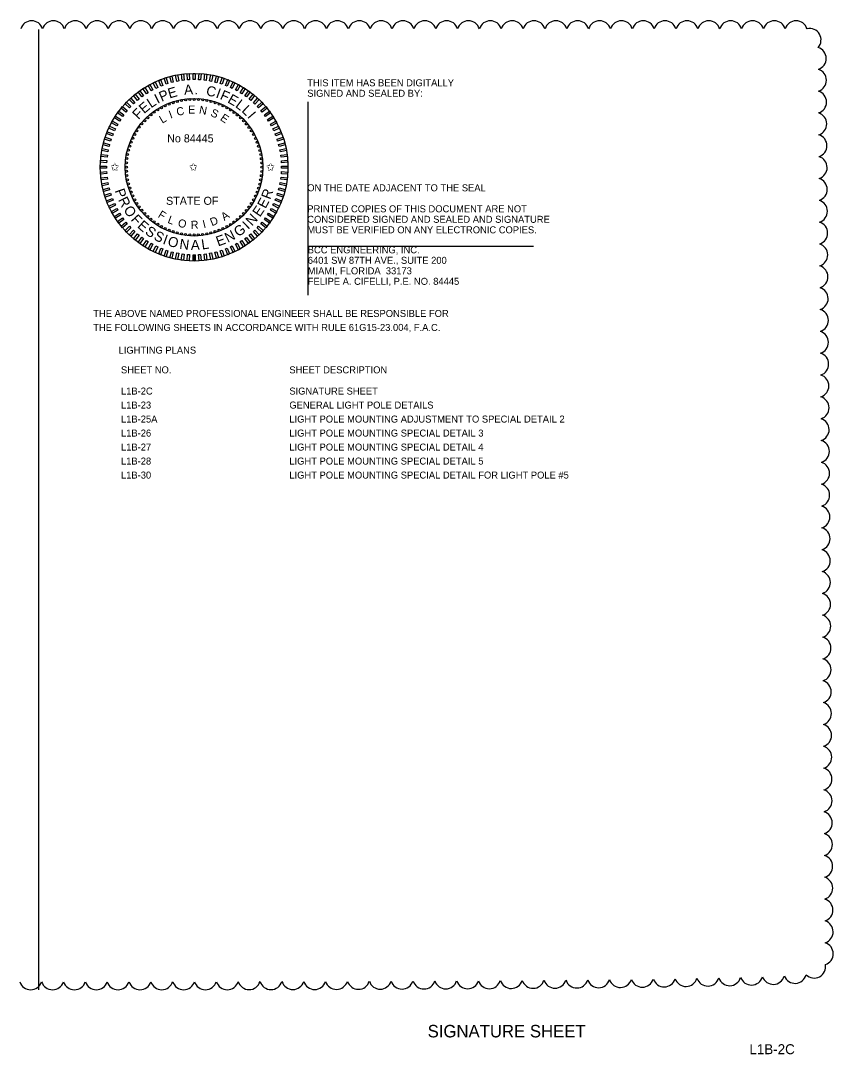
# Model space of a CAD drawing. Extents: x -811.2 to -795, y -2307.6 to -2235.1.
# Drawn here: x -803.27 to -795.14, y -2282.69 to -2272.36 of the extents above; entities that cross this region are included whole.
import ezdxf

# ---------------------------------------------------------------- set-up
doc = ezdxf.new("R2010")
doc.units = 0
for name, color, linetype in [('AdhocPoint_dp', 7, 'Continuous'), ('Cloud_dp', 7, 'Continuous'), ('Logo_dp', 7, 'Continuous'), ('NonPlottingEle_dp', 7, 'Continuous'), ('TeleMisc', 7, 'Continuous'), ('TextDetails', 7, 'Continuous'), ('TextMisc', 7, 'Continuous'), ('TextNotes', 7, 'Continuous')]:
    doc.layers.add(name, color=color, linetype=linetype)

msp = doc.modelspace()

# ---------------------------------------------------------------- linework, layer by layer
at = {"layer": 'AdhocPoint_dp'}
for p, q in [((-800.397, -2273.168), (-800.397, -2275.103)), ((-800.397, -2274.613), (-798.141, -2274.613))]:
    msp.add_line(p, q, dxfattribs=at)
at = {"layer": 'Cloud_dp'}
for centre, start, end in [((-803.157, -2272.472), 17.5, 162.5), ((-802.939, -2272.472), 17.5, 162.5), ((-802.721, -2272.472), 17.5, 162.5), ((-802.502, -2272.472), 17.5, 162.5), ((-802.284, -2272.472), 17.5, 162.5), ((-802.066, -2272.472), 17.5, 162.5), ((-801.847, -2272.472), 17.5, 162.5), ((-801.629, -2272.472), 17.5, 162.5), ((-801.411, -2272.472), 17.5, 162.5), ((-801.192, -2272.472), 17.5, 162.5), ((-800.974, -2272.472), 17.5, 162.5), ((-800.756, -2272.472), 17.5, 162.5), ((-800.537, -2272.472), 17.5, 162.5), ((-800.319, -2272.472), 17.5, 162.5), ((-800.101, -2272.472), 17.5, 162.5), ((-799.882, -2272.472), 17.5, 162.5), ((-799.664, -2272.472), 17.5, 162.5), ((-799.446, -2272.472), 17.5, 162.5), ((-799.227, -2272.472), 17.5, 162.5), ((-799.009, -2272.472), 17.5, 162.5), ((-798.791, -2272.472), 17.5, 162.5), ((-798.572, -2272.472), 17.5, 162.5), ((-798.354, -2272.472), 17.5, 162.5), ((-798.136, -2272.472), 17.5, 162.5), ((-797.917, -2272.472), 17.5, 162.5), ((-797.699, -2272.472), 17.5, 162.5), ((-797.481, -2272.472), 17.5, 162.5), ((-797.262, -2272.472), 17.5, 162.5), ((-797.044, -2272.472), 17.5, 162.5), ((-796.826, -2272.472), 17.5, 162.5), ((-796.607, -2272.472), 17.5, 162.5), ((-796.389, -2272.472), 17.5, 162.5), ((-796.171, -2272.472), 17.5, 162.5), ((-795.952, -2272.472), 17.5, 162.5), ((-795.734, -2272.472), 17.5, 162.5), ((-795.516, -2272.472), 17.5, 162.5), ((-795.381, -2272.549), 318.1116, 103.1116), ((-795.329, -2272.734), 287.9529, 72.9529), ((-795.327, -2272.953), 287.9529, 72.9529), ((-795.326, -2273.171), 287.9529, 72.9529), ((-795.324, -2273.389), 287.9529, 72.9529), ((-795.322, -2273.608), 287.9529, 72.9529), ((-795.32, -2273.826), 287.9529, 72.9529), ((-795.319, -2274.044), 287.9529, 72.9529), ((-795.317, -2274.263), 287.9529, 72.9529), ((-795.315, -2274.481), 287.9529, 72.9529), ((-795.314, -2274.699), 287.9529, 72.9529), ((-795.312, -2274.918), 287.9529, 72.9529), ((-795.31, -2275.136), 287.9529, 72.9529), ((-795.308, -2275.354), 287.9529, 72.9529), ((-795.307, -2275.573), 287.9529, 72.9529), ((-795.305, -2275.791), 287.9529, 72.9529), ((-795.303, -2276.009), 287.9529, 72.9529), ((-795.301, -2276.228), 287.9529, 72.9529), ((-795.3, -2276.446), 287.9529, 72.9529), ((-795.298, -2276.664), 287.9529, 72.9529), ((-795.296, -2276.882), 287.9529, 72.9529), ((-795.295, -2277.101), 287.9529, 72.9529), ((-795.293, -2277.319), 287.9527, 72.9527), ((-795.291, -2277.537), 287.9524, 72.9524), ((-795.289, -2277.756), 287.9521, 72.9521), ((-795.288, -2277.974), 287.9519, 72.9519), ((-795.286, -2278.192), 287.9515, 72.9515), ((-795.284, -2278.411), 287.9512, 72.9512), ((-795.282, -2278.629), 287.9508, 72.9508), ((-795.281, -2278.847), 287.9504, 72.9504), ((-795.279, -2279.066), 287.9499, 72.9499), ((-795.277, -2279.284), 287.9494, 72.9494), ((-795.276, -2279.502), 287.9488, 72.9488), ((-795.274, -2279.721), 287.9481, 72.9481), ((-795.272, -2279.939), 287.9473, 72.9473), ((-795.271, -2280.157), 287.9464, 72.9464), ((-795.269, -2280.376), 287.9452, 72.9452), ((-795.267, -2280.594), 287.9438, 72.9438), ((-795.265, -2280.812), 287.9419, 72.9419), ((-795.264, -2281.03), 287.9394, 72.9394), ((-795.262, -2281.249), 287.9355, 72.9355), ((-795.26, -2281.467), 287.9288, 72.9288), ((-795.259, -2281.685), 287.9106, 72.9106), ((-795.336, -2281.815), 225.4798, 10.4798), ((-803.166, -2281.932), 197.496, 342.496), ((-802.948, -2281.932), 197.5011, 342.5011), ((-802.729, -2281.932), 197.5111, 342.5111), ((-802.511, -2281.932), 197.522, 342.522), ((-802.293, -2281.932), 197.5335, 342.5335), ((-802.074, -2281.932), 197.5456, 342.5456), ((-801.856, -2281.931), 197.5582, 342.5582), ((-801.638, -2281.931), 197.5715, 342.5715), ((-801.42, -2281.931), 197.5855, 342.5855), ((-801.201, -2281.931), 197.6002, 342.6002), ((-800.983, -2281.93), 197.6157, 342.6157), ((-800.765, -2281.93), 197.6322, 342.6322), ((-800.546, -2281.929), 197.6497, 342.6497), ((-800.328, -2281.929), 197.6683, 342.6683), ((-800.11, -2281.928), 197.6881, 342.6881), ((-799.891, -2281.927), 197.7093, 342.7093), ((-799.673, -2281.926), 197.732, 342.732), ((-799.455, -2281.925), 197.7565, 342.7565), ((-799.236, -2281.924), 197.7829, 342.7829), ((-799.018, -2281.923), 197.8116, 342.8116), ((-798.8, -2281.922), 197.8429, 342.8429), ((-798.582, -2281.921), 197.8771, 342.8771), ((-798.363, -2281.919), 197.9149, 342.9149), ((-798.145, -2281.917), 197.9569, 342.9569), ((-797.927, -2281.916), 198.0039, 343.0039), ((-797.708, -2281.914), 198.0569, 343.0569), ((-797.49, -2281.911), 198.1174, 343.1174), ((-797.272, -2281.909), 198.1874, 343.1874), ((-797.054, -2281.906), 198.2696, 343.2696), ((-796.835, -2281.903), 198.368, 343.368), ((-796.617, -2281.899), 198.4888, 343.4888), ((-796.399, -2281.895), 198.642, 343.642), ((-796.181, -2281.891), 198.8454, 343.8454), ((-795.963, -2281.885), 199.1345, 344.1345), ((-795.745, -2281.878), 199.5943, 344.5943), ((-795.527, -2281.868), 200.5167, 345.5167)]:
    msp.add_arc(centre, 0.114, start, end, dxfattribs=at)
at = {"layer": 'TextDetails'}
for radius in [0.938, 0.688]:
    msp.add_circle((-801.533, -2273.822), radius, dxfattribs=at)
at = {"layer": 'TextMisc'}
for p, q in [((-801.543, -2274.759), (-801.543, -2274.697)), ((-801.533, -2274.759), (-801.533, -2274.697)), ((-801.523, -2274.759), (-801.523, -2274.696))]:
    msp.add_line(p, q, dxfattribs=at)
for points in [[(-801.578, -2272.948), (-801.598, -2272.949), (-801.602, -2272.887), (-801.582, -2272.885)], [(-801.523, -2272.946), (-801.543, -2272.946), (-801.543, -2272.884), (-801.523, -2272.884)], [(-801.468, -2272.949), (-801.488, -2272.948), (-801.484, -2272.885), (-801.464, -2272.887)], [(-801.896, -2273.025), (-801.915, -2273.034), (-801.941, -2272.978), (-801.923, -2272.969)], [(-801.846, -2273.004), (-801.864, -2273.012), (-801.887, -2272.954), (-801.869, -2272.946)], [(-801.794, -2272.986), (-801.813, -2272.992), (-801.832, -2272.933), (-801.813, -2272.927)], [(-801.741, -2272.971), (-801.76, -2272.976), (-801.776, -2272.916), (-801.756, -2272.911)], [(-801.687, -2272.96), (-801.707, -2272.964), (-801.718, -2272.903), (-801.699, -2272.899)], [(-801.632, -2272.952), (-801.653, -2272.955), (-801.66, -2272.893), (-801.64, -2272.89)], [(-801.413, -2272.955), (-801.433, -2272.952), (-801.425, -2272.89), (-801.405, -2272.893)], [(-801.359, -2272.964), (-801.379, -2272.96), (-801.367, -2272.899), (-801.347, -2272.903)], [(-801.305, -2272.977), (-801.325, -2272.971), (-801.309, -2272.911), (-801.29, -2272.916)], [(-801.253, -2272.992), (-801.272, -2272.986), (-801.253, -2272.927), (-801.234, -2272.933)], [(-801.201, -2273.012), (-801.22, -2273.004), (-801.197, -2272.946), (-801.178, -2272.954)], [(-801.151, -2273.034), (-801.169, -2273.025), (-801.143, -2272.969), (-801.125, -2272.978)], [(-802.083, -2273.141), (-802.098, -2273.154), (-802.138, -2273.106), (-802.123, -2273.093)], [(-802.039, -2273.108), (-802.055, -2273.119), (-802.092, -2273.069), (-802.076, -2273.057)], [(-801.993, -2273.077), (-802.01, -2273.088), (-802.044, -2273.035), (-802.027, -2273.025)], [(-801.946, -2273.05), (-801.963, -2273.06), (-801.993, -2273.005), (-801.976, -2272.995)], [(-801.102, -2273.06), (-801.12, -2273.05), (-801.09, -2272.995), (-801.072, -2273.005)], [(-801.055, -2273.088), (-801.073, -2273.077), (-801.039, -2273.025), (-801.022, -2273.035)], [(-801.01, -2273.12), (-801.027, -2273.108), (-800.99, -2273.057), (-800.974, -2273.069)], [(-800.967, -2273.154), (-800.983, -2273.141), (-800.943, -2273.093), (-800.928, -2273.106)], [(-802.164, -2273.215), (-802.178, -2273.23), (-802.223, -2273.187), (-802.209, -2273.172)], [(-802.124, -2273.177), (-802.139, -2273.19), (-802.182, -2273.145), (-802.167, -2273.131)], [(-800.926, -2273.191), (-800.941, -2273.177), (-800.898, -2273.131), (-800.884, -2273.145)], [(-800.888, -2273.23), (-800.902, -2273.215), (-800.856, -2273.172), (-800.843, -2273.187)], [(-802.235, -2273.299), (-802.247, -2273.315), (-802.297, -2273.279), (-802.285, -2273.262)], [(-802.201, -2273.256), (-802.214, -2273.271), (-802.262, -2273.232), (-802.249, -2273.216)], [(-800.852, -2273.272), (-800.865, -2273.256), (-800.817, -2273.216), (-800.804, -2273.232)], [(-800.819, -2273.315), (-800.831, -2273.299), (-800.78, -2273.262), (-800.769, -2273.279)], [(-802.295, -2273.391), (-802.305, -2273.409), (-802.359, -2273.379), (-802.35, -2273.361)], [(-802.266, -2273.344), (-802.277, -2273.361), (-802.33, -2273.328), (-802.319, -2273.311)], [(-800.789, -2273.361), (-800.799, -2273.344), (-800.747, -2273.311), (-800.736, -2273.328)], [(-800.761, -2273.409), (-800.771, -2273.391), (-800.716, -2273.361), (-800.707, -2273.379)], [(-802.343, -2273.49), (-802.35, -2273.509), (-802.408, -2273.486), (-802.401, -2273.467)], [(-802.32, -2273.44), (-802.329, -2273.458), (-802.385, -2273.431), (-802.377, -2273.413)], [(-800.737, -2273.458), (-800.745, -2273.44), (-800.689, -2273.413), (-800.68, -2273.432)], [(-800.716, -2273.509), (-800.723, -2273.49), (-800.665, -2273.467), (-800.658, -2273.486)], [(-802.378, -2273.594), (-802.383, -2273.614), (-802.443, -2273.598), (-802.438, -2273.579)], [(-802.362, -2273.541), (-802.368, -2273.561), (-802.428, -2273.541), (-802.421, -2273.522)], [(-800.698, -2273.561), (-800.704, -2273.542), (-800.644, -2273.522), (-800.638, -2273.542)], [(-800.683, -2273.614), (-800.688, -2273.594), (-800.627, -2273.579), (-800.622, -2273.598)], [(-802.4, -2273.702), (-802.402, -2273.722), (-802.464, -2273.714), (-802.462, -2273.694)], [(-802.391, -2273.648), (-802.394, -2273.667), (-802.456, -2273.656), (-802.452, -2273.636)], [(-800.671, -2273.668), (-800.675, -2273.648), (-800.614, -2273.636), (-800.61, -2273.656)], [(-800.664, -2273.722), (-800.666, -2273.702), (-800.604, -2273.694), (-800.602, -2273.714)], [(-802.408, -2273.811), (-802.408, -2273.832), (-802.47, -2273.832), (-802.47, -2273.811)], [(-802.406, -2273.756), (-802.407, -2273.777), (-802.469, -2273.773), (-802.468, -2273.752)], [(-800.659, -2273.777), (-800.66, -2273.757), (-800.598, -2273.753), (-800.597, -2273.773)], [(-800.658, -2273.832), (-800.658, -2273.812), (-800.595, -2273.812), (-800.595, -2273.832)], [(-802.407, -2273.866), (-802.406, -2273.886), (-802.468, -2273.89), (-802.469, -2273.87)], [(-802.402, -2273.921), (-802.4, -2273.941), (-802.462, -2273.949), (-802.464, -2273.929)], [(-800.66, -2273.887), (-800.659, -2273.866), (-800.597, -2273.87), (-800.598, -2273.891)], [(-802.394, -2273.975), (-802.391, -2273.995), (-802.452, -2274.007), (-802.456, -2273.987)], [(-800.675, -2273.995), (-800.672, -2273.976), (-800.61, -2273.987), (-800.614, -2274.007)], [(-800.666, -2273.941), (-800.664, -2273.921), (-800.602, -2273.929), (-800.604, -2273.949)], [(-802.383, -2274.029), (-802.378, -2274.049), (-802.438, -2274.064), (-802.443, -2274.045)], [(-802.368, -2274.082), (-802.362, -2274.101), (-802.421, -2274.121), (-802.428, -2274.102)], [(-800.704, -2274.102), (-800.698, -2274.082), (-800.638, -2274.102), (-800.644, -2274.121)], [(-800.688, -2274.049), (-800.683, -2274.029), (-800.622, -2274.045), (-800.627, -2274.065)], [(-802.35, -2274.134), (-802.343, -2274.153), (-802.401, -2274.176), (-802.408, -2274.157)], [(-802.329, -2274.185), (-802.32, -2274.203), (-802.377, -2274.23), (-802.386, -2274.211)], [(-800.746, -2274.203), (-800.737, -2274.185), (-800.68, -2274.212), (-800.689, -2274.23)], [(-800.723, -2274.153), (-800.716, -2274.134), (-800.658, -2274.157), (-800.665, -2274.176)], [(-802.305, -2274.234), (-802.295, -2274.252), (-802.35, -2274.282), (-802.359, -2274.264)], [(-802.277, -2274.282), (-802.266, -2274.299), (-802.319, -2274.332), (-802.33, -2274.315)], [(-802.247, -2274.328), (-802.235, -2274.344), (-802.285, -2274.381), (-802.297, -2274.364)], [(-800.831, -2274.344), (-800.819, -2274.328), (-800.769, -2274.364), (-800.78, -2274.381)], [(-800.8, -2274.299), (-800.789, -2274.282), (-800.736, -2274.315), (-800.747, -2274.332)], [(-800.771, -2274.252), (-800.761, -2274.234), (-800.707, -2274.264), (-800.716, -2274.282)], [(-802.214, -2274.371), (-802.201, -2274.387), (-802.249, -2274.427), (-802.262, -2274.411)], [(-802.178, -2274.413), (-802.164, -2274.428), (-802.209, -2274.471), (-802.223, -2274.456)], [(-800.902, -2274.428), (-800.888, -2274.413), (-800.843, -2274.456), (-800.857, -2274.471)], [(-800.865, -2274.387), (-800.852, -2274.372), (-800.804, -2274.411), (-800.817, -2274.427)], [(-802.139, -2274.452), (-802.125, -2274.466), (-802.167, -2274.512), (-802.182, -2274.498)], [(-802.099, -2274.489), (-802.083, -2274.502), (-802.123, -2274.55), (-802.138, -2274.537)], [(-802.055, -2274.523), (-802.039, -2274.535), (-802.076, -2274.586), (-802.092, -2274.574)], [(-801.027, -2274.535), (-801.011, -2274.524), (-800.974, -2274.574), (-800.99, -2274.586)], [(-800.983, -2274.502), (-800.967, -2274.489), (-800.928, -2274.537), (-800.943, -2274.55)], [(-800.941, -2274.466), (-800.927, -2274.453), (-800.884, -2274.498), (-800.899, -2274.512)], [(-802.01, -2274.555), (-801.993, -2274.566), (-802.027, -2274.618), (-802.044, -2274.608)], [(-801.963, -2274.583), (-801.946, -2274.593), (-801.976, -2274.648), (-801.993, -2274.638)], [(-801.915, -2274.609), (-801.896, -2274.618), (-801.923, -2274.674), (-801.941, -2274.665)], [(-801.865, -2274.631), (-801.846, -2274.639), (-801.869, -2274.697), (-801.887, -2274.689)], [(-801.22, -2274.639), (-801.202, -2274.631), (-801.179, -2274.689), (-801.197, -2274.697)], [(-801.17, -2274.618), (-801.151, -2274.609), (-801.125, -2274.665), (-801.143, -2274.674)], [(-801.12, -2274.593), (-801.103, -2274.583), (-801.073, -2274.638), (-801.09, -2274.648)], [(-801.073, -2274.566), (-801.056, -2274.555), (-801.022, -2274.608), (-801.039, -2274.618)], [(-801.813, -2274.651), (-801.794, -2274.657), (-801.813, -2274.716), (-801.832, -2274.71)], [(-801.76, -2274.667), (-801.741, -2274.672), (-801.756, -2274.732), (-801.776, -2274.727)], [(-801.707, -2274.679), (-801.687, -2274.683), (-801.699, -2274.744), (-801.719, -2274.74)], [(-801.653, -2274.688), (-801.633, -2274.691), (-801.64, -2274.753), (-801.661, -2274.75)], [(-801.598, -2274.694), (-801.578, -2274.695), (-801.582, -2274.758), (-801.602, -2274.756)], [(-801.543, -2274.697), (-801.523, -2274.697), (-801.523, -2274.759), (-801.543, -2274.759)], [(-801.488, -2274.695), (-801.468, -2274.694), (-801.464, -2274.756), (-801.484, -2274.758)], [(-801.433, -2274.691), (-801.413, -2274.688), (-801.406, -2274.75), (-801.426, -2274.753)], [(-801.379, -2274.683), (-801.359, -2274.679), (-801.347, -2274.74), (-801.367, -2274.744)], [(-801.325, -2274.672), (-801.306, -2274.667), (-801.29, -2274.727), (-801.31, -2274.732)], [(-801.272, -2274.657), (-801.253, -2274.651), (-801.234, -2274.71), (-801.253, -2274.716)]]:
    msp.add_lwpolyline(points, close=True, dxfattribs=at)
for centre in [(-801.782, -2273.191), (-801.742, -2273.177), (-801.701, -2273.165), (-801.659, -2273.156), (-801.617, -2273.149), (-801.575, -2273.145), (-801.532, -2273.144), (-801.49, -2273.145), (-801.447, -2273.149), (-801.405, -2273.156), (-801.364, -2273.165), (-801.323, -2273.177), (-801.283, -2273.192), (-801.964, -2273.299), (-801.931, -2273.273), (-801.895, -2273.249), (-801.859, -2273.228), (-801.821, -2273.208), (-801.244, -2273.209), (-801.206, -2273.228), (-801.169, -2273.25), (-801.134, -2273.274), (-801.101, -2273.3), (-802.055, -2273.389), (-802.026, -2273.357), (-801.996, -2273.327), (-801.069, -2273.328), (-801.039, -2273.358), (-801.011, -2273.39), (-802.126, -2273.495), (-802.105, -2273.458), (-802.081, -2273.423), (-800.985, -2273.424), (-800.961, -2273.459), (-800.939, -2273.496), (-802.177, -2273.612), (-802.163, -2273.572), (-802.146, -2273.533), (-800.92, -2273.534), (-800.903, -2273.573), (-800.888, -2273.613), (-802.198, -2273.694), (-802.189, -2273.652), (-800.877, -2273.654), (-800.867, -2273.695), (-802.21, -2273.821), (-802.209, -2273.778), (-802.205, -2273.736), (-800.861, -2273.737), (-800.857, -2273.78), (-800.855, -2273.822), (-802.209, -2273.863), (-802.205, -2273.906), (-800.861, -2273.907), (-800.857, -2273.865), (-802.198, -2273.948), (-802.189, -2273.989), (-802.177, -2274.03), (-800.889, -2274.031), (-800.877, -2273.991), (-800.868, -2273.949), (-802.163, -2274.07), (-802.146, -2274.109), (-800.92, -2274.11), (-800.903, -2274.071), (-802.127, -2274.147), (-802.105, -2274.184), (-802.081, -2274.219), (-800.985, -2274.22), (-800.961, -2274.185), (-800.94, -2274.148), (-802.055, -2274.253), (-802.027, -2274.285), (-801.997, -2274.315), (-801.965, -2274.343), (-801.102, -2274.344), (-801.07, -2274.316), (-801.039, -2274.286), (-801.011, -2274.254), (-801.932, -2274.369), (-801.896, -2274.393), (-801.86, -2274.415), (-801.822, -2274.434), (-801.245, -2274.435), (-801.207, -2274.415), (-801.17, -2274.394), (-801.135, -2274.37), (-801.783, -2274.451), (-801.743, -2274.466), (-801.702, -2274.478), (-801.66, -2274.487), (-801.618, -2274.494), (-801.576, -2274.498), (-801.533, -2274.499), (-801.491, -2274.498), (-801.449, -2274.494), (-801.407, -2274.487), (-801.365, -2274.478), (-801.324, -2274.466), (-801.284, -2274.452)]:
    msp.add_circle(centre, 0.01, dxfattribs=at)
at = {"layer": 'TextNotes'}
msp.add_line((-803.086, -2282.046), (-803.086, -2272.446), dxfattribs=at)

# ---------------------------------------------------------------- texts
at = {"layer": 'Logo_dp'}
for s, height, p in [('THIS ITEM HAS BEEN DIGITALLY', 0.07, (-800.402, -2273.013)), ('SIGNED AND SEALED BY:', 0.07, (-800.402, -2273.118)), ('ON THE DATE ADJACENT TO THE SEAL', 0.07, (-800.402, -2274.063)), ('PRINTED COPIES OF THIS DOCUMENT ARE NOT ', 0.07, (-800.402, -2274.273)), ('CONSIDERED SIGNED AND SEALED AND SIGNATURE ', 0.07, (-800.402, -2274.378)), ('MUST BE VERIFIED ON ANY ELECTRONIC COPIES.', 0.07, (-800.402, -2274.483)), ('BCC ENGINEERING, INC.', 0.07, (-800.397, -2274.683)), ('6401 SW 87TH AVE., SUITE 200', 0.07, (-800.397, -2274.788)), ('MIAMI, FLORIDA  33173', 0.07, (-800.397, -2274.893)), ('FELIPE A. CIFELLI, P.E. NO. 84445', 0.07, (-800.397, -2274.998)), ('THE ABOVE NAMED PROFESSIONAL ENGINEER SHALL BE RESPONSIBLE FOR ', 0.07, (-802.541, -2275.319)), ('THE FOLLOWING SHEETS IN ACCORDANCE WITH RULE 61G15-23.004, F.A.C.', 0.07, (-802.541, -2275.459)), ('LIGHTING PLANS', 0.07, (-802.288, -2275.686)), ('       SIGNATURE SHEET         ', 0.125, (-799.524, -2282.522))]:
    msp.add_text(s, height=height, dxfattribs=at).set_placement(p)
at = {"layer": 'NonPlottingEle_dp'}
msp.add_text('L1B-2C ', height=0.1, dxfattribs=at).set_placement((-795.983, -2282.69))
at = {"layer": 'TeleMisc'}
for s, p in [('SHEET NO.', (-802.264, -2275.883)), ('SHEET DESCRIPTION', (-800.581, -2275.883)), ('L1B-2C', (-802.264, -2276.095)), ('SIGNATURE SHEET', (-800.581, -2276.095)), ('L1B-23', (-802.264, -2276.235)), ('GENERAL LIGHT POLE DETAILS', (-800.581, -2276.235)), ('L1B-25A', (-802.264, -2276.375)), ('LIGHT POLE MOUNTING ADJUSTMENT TO SPECIAL DETAIL 2', (-800.581, -2276.375)), ('L1B-26', (-802.264, -2276.515)), ('LIGHT POLE MOUNTING SPECIAL DETAIL 3', (-800.581, -2276.515)), ('L1B-27', (-802.264, -2276.655)), ('LIGHT POLE MOUNTING SPECIAL DETAIL 4', (-800.581, -2276.655)), ('L1B-28', (-802.264, -2276.795)), ('LIGHT POLE MOUNTING SPECIAL DETAIL 5', (-800.581, -2276.795)), ('L1B-30', (-802.264, -2276.935)), ('LIGHT POLE MOUNTING SPECIAL DETAIL FOR LIGHT POLE #5', (-800.581, -2276.935))]:
    msp.add_text(s, height=0.07, dxfattribs=at).set_placement(p)
at = {"layer": 'TextMisc'}
for s, height, rotation, p in [('I', 0.1, 26.8161, (-801.898, -2273.191)), ('P', 0.1, 23.2829, (-801.858, -2273.169)), ('E', 0.1, 16.5426, (-801.779, -2273.136)), ('A', 0.1, 4.421, (-801.63, -2273.099)), ('.', 0.1, 356.654, (-801.531, -2273.093)), ('C', 0.1, 347.7999, (-801.419, -2273.102)), ('I', 0.1, 340.0631, (-801.323, -2273.124)), ('F', 0.1, 336.5299, (-801.281, -2273.138)), ('E', 0.1, 330.0796, (-801.206, -2273.171)), ('E', 0.1, 40.1214, (-802.033, -2273.292)), ('L', 0.1, 33.0792, (-801.964, -2273.234)), ('L', 0.1, 323.0373, (-801.128, -2273.216)), ('F', 0.1, 46.5718, (-802.089, -2273.351)), ('I', 0.08, 20.0117, (-801.769, -2273.337)), ('C', 0.08, 12.2025, (-801.701, -2273.31)), ('E', 0.08, 0.4186, (-801.593, -2273.286)), ('N', 0.08, 349.2914, (-801.488, -2273.285)), ('S', 0.08, 337.0221, (-801.375, -2273.307)), ('E', 0.08, 325.8663, (-801.279, -2273.347)), ('L', 0.1, 316.7742, (-801.065, -2273.263)), ('I', 0.1, 310.5111, (-801.006, -2273.318)), ('L', 0.08, 30.4021, (-801.852, -2273.388)), ('P', 0.1, 289.4055, (-802.328, -2274.056)), ('R', 0.1, 296.1458, (-802.295, -2274.148)), ('E', 0.1, 62.4712, (-800.819, -2274.242)), ('R', 0.1, 69.5134, (-800.773, -2274.151)), ('O', 0.1, 303.9671, (-802.243, -2274.248)), ('E', 0.1, 55.4289, (-800.876, -2274.326)), ('F', 0.1, 312.628, (-802.171, -2274.35)), ('F', 0.08, 328.7241, (-801.901, -2274.318)), ('L', 0.08, 339.2916, (-801.804, -2274.377)), ('D', 0.08, 22.0128, (-801.355, -2274.413)), ('A', 0.08, 34.4992, (-801.231, -2274.361)), ('N', 0.1, 47.1788, (-800.955, -2274.415)), ('E', 0.1, 319.0783, (-802.107, -2274.419)), ('S', 0.1, 326.1206, (-802.03, -2274.485)), ('O', 0.08, 349.6821, (-801.699, -2274.417)), ('R', 0.08, 2.3398, (-801.565, -2274.439)), ('I', 0.08, 14.2037, (-801.437, -2274.432)), ('G', 0.1, 35.1115, (-801.092, -2274.523)), ('I', 0.1, 43.6456, (-800.993, -2274.45)), ('S', 0.1, 333.193, (-801.944, -2274.541)), ('I', 0.1, 340.2654, (-801.853, -2274.586)), ('O', 0.1, 343.7986, (-801.805, -2274.604)), ('N', 0.1, 352.4595, (-801.684, -2274.636)), ('E', 0.1, 19.8191, (-801.293, -2274.615)), ('N', 0.1, 26.8614, (-801.197, -2274.579)), ('A', 0.1, 0.7097, (-801.565, -2274.649)), ('L', 0.1, 8.4767, (-801.453, -2274.646))]:
    msp.add_text(s, height=height, rotation=rotation, dxfattribs=at).set_placement(p)
for s, p in [('No 84445', (-801.802, -2273.574)), ('✩', (-802.368, -2273.859)), ('✩', (-801.583, -2273.859)), ('✩', (-800.811, -2273.859)), ('STATE OF', (-801.813, -2274.198))]:
    msp.add_text(s, height=0.08, dxfattribs=at).set_placement(p)

doc.saveas('drawing.dxf')
